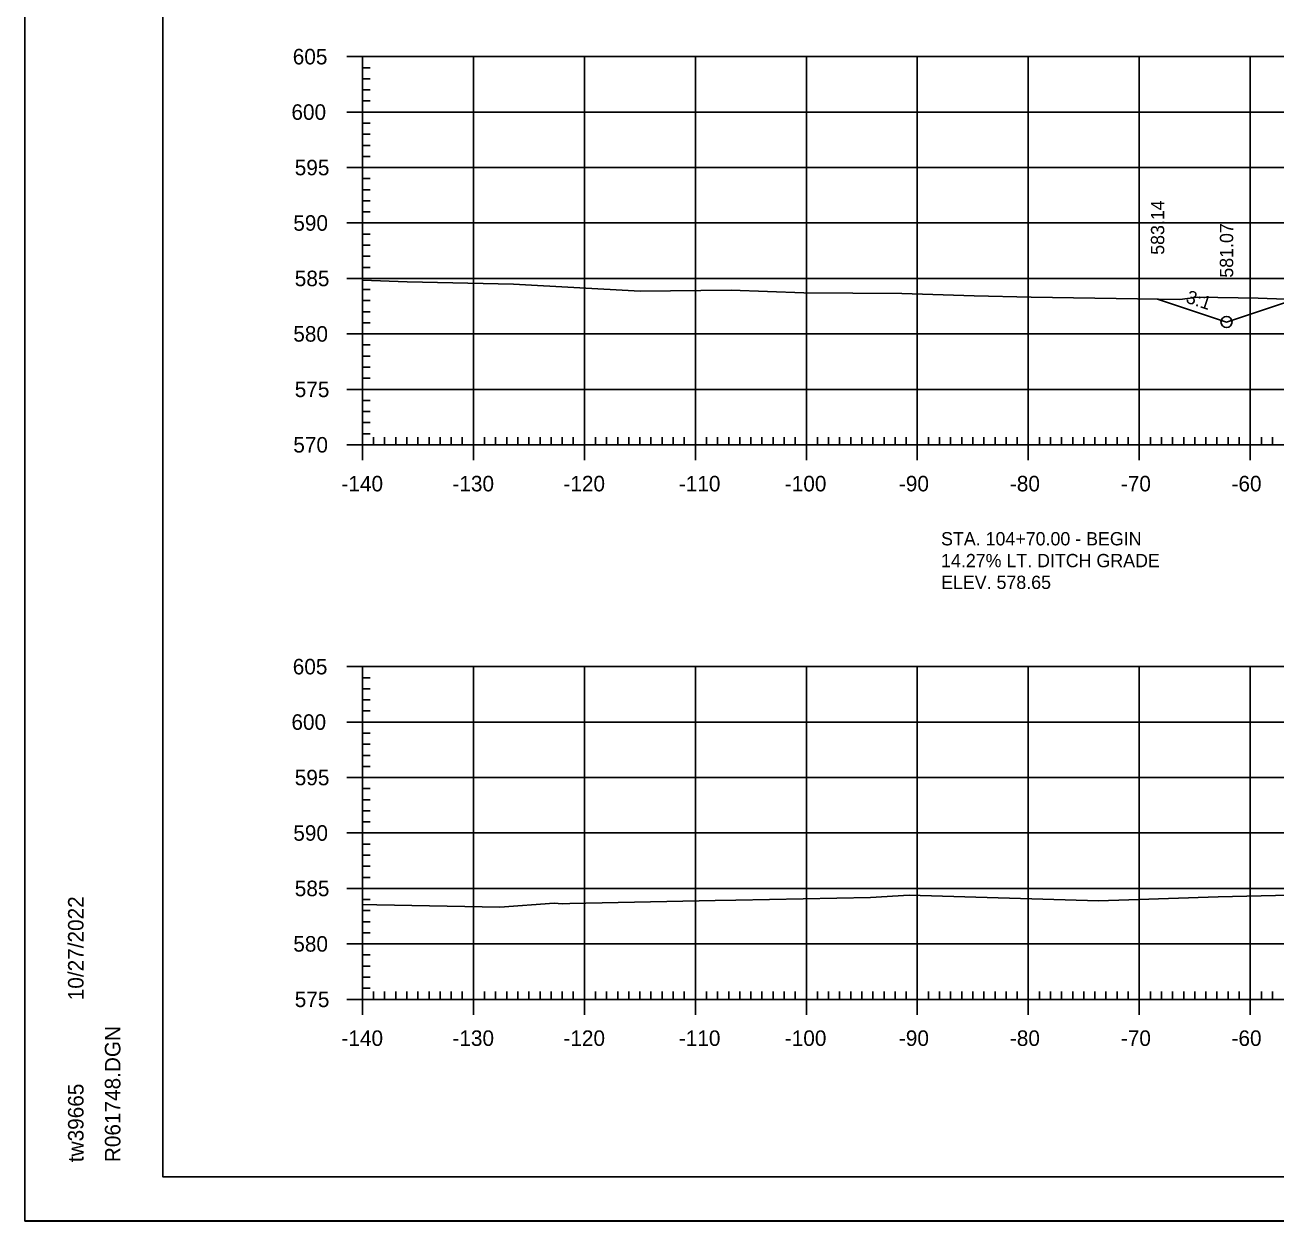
# Model space of a CAD drawing. Extents: x 961436 to 1372525, y 380079 to 2027791.
# Drawn here: x 1370463.4 to 1370576.1, y 380322.4 to 380430.3 of the extents above; entities that cross this region are included whole.
import ezdxf

# ---------------------------------------------------------------- set-up
doc = ezdxf.new("R2010")
doc.units = 0
for name, color, linetype in [('R_Axis', 7, 'Continuous'), ('R_Axis Annot', 7, 'Continuous'), ('R_Exist Surface', 7, 'Continuous'), ('R_Fin Surface', 7, 'Continuous'), ('R_Fin Surface Annot', 7, 'Continuous'), ('R_Grid', 7, 'Continuous'), ('R_No Plot', 7, 'Continuous')]:
    doc.layers.add(name, color=color, linetype=linetype)

msp = doc.modelspace()

# ---------------------------------------------------------------- linework, layer by layer
at = {"layer": 'R_Axis'}
for p, q in [((1370492.41, 380427.4), (1370495.21, 380427.4)), ((1370493.81, 380392.4), (1370493.81, 380427.4)), ((1370493.81, 380426.4), (1370494.51, 380426.4)), ((1370493.81, 380425.4), (1370494.51, 380425.4)), ((1370493.81, 380424.4), (1370494.51, 380424.4)), ((1370493.81, 380423.4), (1370494.51, 380423.4)), ((1370492.41, 380422.4), (1370495.21, 380422.4)), ((1370493.81, 380421.4), (1370494.51, 380421.4)), ((1370493.81, 380420.4), (1370494.51, 380420.4)), ((1370493.81, 380419.4), (1370494.51, 380419.4)), ((1370492.41, 380417.4), (1370495.21, 380417.4)), ((1370493.81, 380418.4), (1370494.51, 380418.4)), ((1370493.81, 380416.4), (1370494.51, 380416.4)), ((1370493.81, 380415.4), (1370494.51, 380415.4)), ((1370493.81, 380414.4), (1370494.51, 380414.4)), ((1370493.81, 380413.4), (1370494.51, 380413.4)), ((1370492.41, 380412.4), (1370495.21, 380412.4)), ((1370493.81, 380411.4), (1370494.51, 380411.4)), ((1370493.81, 380410.4), (1370494.51, 380410.4)), ((1370493.81, 380409.4), (1370494.51, 380409.4)), ((1370493.81, 380408.4), (1370494.51, 380408.4)), ((1370492.41, 380407.4), (1370495.21, 380407.4)), ((1370493.81, 380406.4), (1370494.51, 380406.4)), ((1370493.81, 380405.4), (1370494.51, 380405.4)), ((1370493.81, 380404.4), (1370494.51, 380404.4)), ((1370493.81, 380403.4), (1370494.51, 380403.4)), ((1370492.41, 380402.4), (1370495.21, 380402.4)), ((1370493.81, 380401.4), (1370494.51, 380401.4)), ((1370493.81, 380400.4), (1370494.51, 380400.4)), ((1370493.81, 380399.4), (1370494.51, 380399.4)), ((1370493.81, 380398.4), (1370494.51, 380398.4)), ((1370492.41, 380397.4), (1370495.21, 380397.4)), ((1370493.81, 380396.4), (1370494.51, 380396.4)), ((1370493.81, 380395.4), (1370494.51, 380395.4)), ((1370493.81, 380394.4), (1370494.51, 380394.4)), ((1370493.81, 380391), (1370493.81, 380393.8)), ((1370503.81, 380391), (1370503.81, 380393.8)), ((1370513.81, 380391), (1370513.81, 380393.8)), ((1370523.81, 380391), (1370523.81, 380393.8)), ((1370533.81, 380391), (1370533.81, 380393.8)), ((1370543.81, 380391), (1370543.81, 380393.8)), ((1370553.81, 380391), (1370553.81, 380393.8)), ((1370563.81, 380391), (1370563.81, 380393.8)), ((1370573.81, 380391), (1370573.81, 380393.8)), ((1370493.81, 380393.4), (1370494.51, 380393.4)), ((1370494.81, 380392.4), (1370494.81, 380393.1)), ((1370495.81, 380392.4), (1370495.81, 380393.1)), ((1370496.81, 380392.4), (1370496.81, 380393.1)), ((1370497.81, 380392.4), (1370497.81, 380393.1)), ((1370498.81, 380392.4), (1370498.81, 380393.1)), ((1370499.81, 380392.4), (1370499.81, 380393.1)), ((1370500.81, 380392.4), (1370500.81, 380393.1)), ((1370501.81, 380392.4), (1370501.81, 380393.1)), ((1370502.81, 380392.4), (1370502.81, 380393.1)), ((1370504.81, 380392.4), (1370504.81, 380393.1)), ((1370505.81, 380392.4), (1370505.81, 380393.1)), ((1370506.81, 380392.4), (1370506.81, 380393.1)), ((1370507.81, 380392.4), (1370507.81, 380393.1)), ((1370508.81, 380392.4), (1370508.81, 380393.1)), ((1370509.81, 380392.4), (1370509.81, 380393.1)), ((1370510.81, 380392.4), (1370510.81, 380393.1)), ((1370511.81, 380392.4), (1370511.81, 380393.1)), ((1370512.81, 380392.4), (1370512.81, 380393.1)), ((1370514.81, 380392.4), (1370514.81, 380393.1)), ((1370515.81, 380392.4), (1370515.81, 380393.1)), ((1370516.81, 380392.4), (1370516.81, 380393.1)), ((1370517.81, 380392.4), (1370517.81, 380393.1)), ((1370518.81, 380392.4), (1370518.81, 380393.1)), ((1370519.81, 380392.4), (1370519.81, 380393.1)), ((1370520.81, 380392.4), (1370520.81, 380393.1)), ((1370521.81, 380392.4), (1370521.81, 380393.1)), ((1370522.81, 380392.4), (1370522.81, 380393.1)), ((1370524.81, 380392.4), (1370524.81, 380393.1)), ((1370525.81, 380392.4), (1370525.81, 380393.1)), ((1370526.81, 380392.4), (1370526.81, 380393.1)), ((1370527.81, 380392.4), (1370527.81, 380393.1)), ((1370528.81, 380392.4), (1370528.81, 380393.1)), ((1370529.81, 380392.4), (1370529.81, 380393.1)), ((1370530.81, 380392.4), (1370530.81, 380393.1)), ((1370531.81, 380392.4), (1370531.81, 380393.1)), ((1370532.81, 380392.4), (1370532.81, 380393.1)), ((1370534.81, 380392.4), (1370534.81, 380393.1)), ((1370535.81, 380392.4), (1370535.81, 380393.1)), ((1370536.81, 380392.4), (1370536.81, 380393.1)), ((1370537.81, 380392.4), (1370537.81, 380393.1)), ((1370538.81, 380392.4), (1370538.81, 380393.1)), ((1370539.81, 380392.4), (1370539.81, 380393.1)), ((1370540.81, 380392.4), (1370540.81, 380393.1)), ((1370541.81, 380392.4), (1370541.81, 380393.1)), ((1370542.81, 380392.4), (1370542.81, 380393.1)), ((1370544.81, 380392.4), (1370544.81, 380393.1)), ((1370545.81, 380392.4), (1370545.81, 380393.1)), ((1370546.81, 380392.4), (1370546.81, 380393.1)), ((1370547.81, 380392.4), (1370547.81, 380393.1)), ((1370548.81, 380392.4), (1370548.81, 380393.1)), ((1370549.81, 380392.4), (1370549.81, 380393.1)), ((1370550.81, 380392.4), (1370550.81, 380393.1)), ((1370551.81, 380392.4), (1370551.81, 380393.1)), ((1370552.81, 380392.4), (1370552.81, 380393.1)), ((1370554.81, 380392.4), (1370554.81, 380393.1)), ((1370555.81, 380392.4), (1370555.81, 380393.1)), ((1370556.81, 380392.4), (1370556.81, 380393.1)), ((1370557.81, 380392.4), (1370557.81, 380393.1)), ((1370558.81, 380392.4), (1370558.81, 380393.1)), ((1370559.81, 380392.4), (1370559.81, 380393.1)), ((1370560.81, 380392.4), (1370560.81, 380393.1)), ((1370561.81, 380392.4), (1370561.81, 380393.1)), ((1370562.81, 380392.4), (1370562.81, 380393.1)), ((1370564.81, 380392.4), (1370564.81, 380393.1)), ((1370565.81, 380392.4), (1370565.81, 380393.1)), ((1370566.81, 380392.4), (1370566.81, 380393.1)), ((1370567.81, 380392.4), (1370567.81, 380393.1)), ((1370568.81, 380392.4), (1370568.81, 380393.1)), ((1370569.81, 380392.4), (1370569.81, 380393.1)), ((1370570.81, 380392.4), (1370570.81, 380393.1)), ((1370571.81, 380392.4), (1370571.81, 380393.1)), ((1370572.81, 380392.4), (1370572.81, 380393.1)), ((1370574.81, 380392.4), (1370574.81, 380393.1)), ((1370575.81, 380392.4), (1370575.81, 380393.1)), ((1370492.41, 380392.4), (1370495.21, 380392.4)), ((1370493.81, 380392.4), (1370773.81, 380392.4)), ((1370492.41, 380372.4), (1370495.21, 380372.4)), ((1370493.81, 380342.4), (1370493.81, 380372.4)), ((1370493.81, 380371.4), (1370494.51, 380371.4)), ((1370493.81, 380370.4), (1370494.51, 380370.4)), ((1370493.81, 380369.4), (1370494.51, 380369.4)), ((1370493.81, 380368.4), (1370494.51, 380368.4)), ((1370492.41, 380367.4), (1370495.21, 380367.4)), ((1370493.81, 380366.4), (1370494.51, 380366.4)), ((1370493.81, 380365.4), (1370494.51, 380365.4)), ((1370493.81, 380364.4), (1370494.51, 380364.4)), ((1370493.81, 380363.4), (1370494.51, 380363.4)), ((1370492.41, 380362.4), (1370495.21, 380362.4)), ((1370493.81, 380361.4), (1370494.51, 380361.4)), ((1370493.81, 380360.4), (1370494.51, 380360.4)), ((1370493.81, 380359.4), (1370494.51, 380359.4)), ((1370493.81, 380358.4), (1370494.51, 380358.4)), ((1370492.41, 380357.4), (1370495.21, 380357.4)), ((1370493.81, 380356.4), (1370494.51, 380356.4)), ((1370493.81, 380355.4), (1370494.51, 380355.4)), ((1370493.81, 380354.4), (1370494.51, 380354.4)), ((1370493.81, 380353.4), (1370494.51, 380353.4)), ((1370492.41, 380352.4), (1370495.21, 380352.4)), ((1370493.81, 380351.4), (1370494.51, 380351.4)), ((1370493.81, 380350.4), (1370494.51, 380350.4)), ((1370493.81, 380349.4), (1370494.51, 380349.4)), ((1370493.81, 380348.4), (1370494.51, 380348.4)), ((1370492.41, 380347.4), (1370495.21, 380347.4)), ((1370493.81, 380346.4), (1370494.51, 380346.4)), ((1370493.81, 380345.4), (1370494.51, 380345.4)), ((1370493.81, 380344.4), (1370494.51, 380344.4)), ((1370493.81, 380341), (1370493.81, 380343.8)), ((1370493.81, 380343.4), (1370494.51, 380343.4)), ((1370494.81, 380342.4), (1370494.81, 380343.1)), ((1370495.81, 380342.4), (1370495.81, 380343.1)), ((1370496.81, 380342.4), (1370496.81, 380343.1)), ((1370497.81, 380342.4), (1370497.81, 380343.1)), ((1370498.81, 380342.4), (1370498.81, 380343.1)), ((1370499.81, 380342.4), (1370499.81, 380343.1)), ((1370500.81, 380342.4), (1370500.81, 380343.1)), ((1370501.81, 380342.4), (1370501.81, 380343.1)), ((1370502.81, 380342.4), (1370502.81, 380343.1)), ((1370503.81, 380341), (1370503.81, 380343.8)), ((1370504.81, 380342.4), (1370504.81, 380343.1)), ((1370505.81, 380342.4), (1370505.81, 380343.1)), ((1370506.81, 380342.4), (1370506.81, 380343.1)), ((1370507.81, 380342.4), (1370507.81, 380343.1)), ((1370508.81, 380342.4), (1370508.81, 380343.1)), ((1370509.81, 380342.4), (1370509.81, 380343.1)), ((1370510.81, 380342.4), (1370510.81, 380343.1)), ((1370511.81, 380342.4), (1370511.81, 380343.1)), ((1370512.81, 380342.4), (1370512.81, 380343.1)), ((1370513.81, 380341), (1370513.81, 380343.8)), ((1370514.81, 380342.4), (1370514.81, 380343.1)), ((1370515.81, 380342.4), (1370515.81, 380343.1)), ((1370516.81, 380342.4), (1370516.81, 380343.1)), ((1370517.81, 380342.4), (1370517.81, 380343.1)), ((1370518.81, 380342.4), (1370518.81, 380343.1)), ((1370519.81, 380342.4), (1370519.81, 380343.1)), ((1370520.81, 380342.4), (1370520.81, 380343.1)), ((1370521.81, 380342.4), (1370521.81, 380343.1)), ((1370522.81, 380342.4), (1370522.81, 380343.1)), ((1370523.81, 380341), (1370523.81, 380343.8)), ((1370524.81, 380342.4), (1370524.81, 380343.1)), ((1370525.81, 380342.4), (1370525.81, 380343.1)), ((1370526.81, 380342.4), (1370526.81, 380343.1)), ((1370527.81, 380342.4), (1370527.81, 380343.1)), ((1370528.81, 380342.4), (1370528.81, 380343.1)), ((1370529.81, 380342.4), (1370529.81, 380343.1)), ((1370530.81, 380342.4), (1370530.81, 380343.1)), ((1370531.81, 380342.4), (1370531.81, 380343.1)), ((1370532.81, 380342.4), (1370532.81, 380343.1)), ((1370533.81, 380341), (1370533.81, 380343.8)), ((1370534.81, 380342.4), (1370534.81, 380343.1)), ((1370535.81, 380342.4), (1370535.81, 380343.1)), ((1370536.81, 380342.4), (1370536.81, 380343.1)), ((1370537.81, 380342.4), (1370537.81, 380343.1)), ((1370538.81, 380342.4), (1370538.81, 380343.1)), ((1370539.81, 380342.4), (1370539.81, 380343.1)), ((1370540.81, 380342.4), (1370540.81, 380343.1)), ((1370541.81, 380342.4), (1370541.81, 380343.1)), ((1370542.81, 380342.4), (1370542.81, 380343.1)), ((1370543.81, 380341), (1370543.81, 380343.8)), ((1370544.81, 380342.4), (1370544.81, 380343.1)), ((1370545.81, 380342.4), (1370545.81, 380343.1)), ((1370546.81, 380342.4), (1370546.81, 380343.1)), ((1370547.81, 380342.4), (1370547.81, 380343.1)), ((1370548.81, 380342.4), (1370548.81, 380343.1)), ((1370549.81, 380342.4), (1370549.81, 380343.1)), ((1370550.81, 380342.4), (1370550.81, 380343.1)), ((1370551.81, 380342.4), (1370551.81, 380343.1)), ((1370552.81, 380342.4), (1370552.81, 380343.1)), ((1370553.81, 380341), (1370553.81, 380343.8)), ((1370554.81, 380342.4), (1370554.81, 380343.1)), ((1370555.81, 380342.4), (1370555.81, 380343.1)), ((1370556.81, 380342.4), (1370556.81, 380343.1)), ((1370557.81, 380342.4), (1370557.81, 380343.1)), ((1370558.81, 380342.4), (1370558.81, 380343.1)), ((1370559.81, 380342.4), (1370559.81, 380343.1)), ((1370560.81, 380342.4), (1370560.81, 380343.1)), ((1370561.81, 380342.4), (1370561.81, 380343.1)), ((1370562.81, 380342.4), (1370562.81, 380343.1)), ((1370563.81, 380341), (1370563.81, 380343.8)), ((1370564.81, 380342.4), (1370564.81, 380343.1)), ((1370565.81, 380342.4), (1370565.81, 380343.1)), ((1370566.81, 380342.4), (1370566.81, 380343.1)), ((1370567.81, 380342.4), (1370567.81, 380343.1)), ((1370568.81, 380342.4), (1370568.81, 380343.1)), ((1370569.81, 380342.4), (1370569.81, 380343.1)), ((1370570.81, 380342.4), (1370570.81, 380343.1)), ((1370571.81, 380342.4), (1370571.81, 380343.1)), ((1370572.81, 380342.4), (1370572.81, 380343.1)), ((1370573.81, 380341), (1370573.81, 380343.8)), ((1370574.81, 380342.4), (1370574.81, 380343.1)), ((1370575.81, 380342.4), (1370575.81, 380343.1)), ((1370492.41, 380342.4), (1370495.21, 380342.4)), ((1370493.81, 380342.4), (1370773.81, 380342.4))]:
    msp.add_line(p, q, dxfattribs=at)
at = {"layer": 'R_Exist Surface'}
for points in [[(1370493.81, 380407.24), (1370497.83, 380407.1), (1370507.43, 380406.87), (1370518.84, 380406.24), (1370527.04, 380406.35), (1370533.59, 380406.11), (1370542.42, 380406.05), (1370548.92, 380405.82), (1370554.07, 380405.71), (1370567.47, 380405.5), (1370569.09, 380405.71), (1370574.52, 380405.61), (1370588.55, 380405.1)], [(1370493.81, 380350.96), (1370495.11, 380350.93), (1370506.18, 380350.72), (1370511.08, 380351.06), (1370511.81, 380351.02), (1370512.5, 380351.03), (1370525.59, 380351.3), (1370527.45, 380351.34), (1370539.6, 380351.58), (1370543.08, 380351.79), (1370560.13, 380351.29), (1370562.86, 380351.36), (1370570.92, 380351.63), (1370576.07, 380351.75), (1370584.56, 380351.96)]]:
    msp.add_lwpolyline(points, dxfattribs=at)
at = {"layer": 'R_Fin Surface'}
msp.add_lwpolyline([(1370565.46, 380405.53), (1370569.6, 380404.16), (1370571.67, 380403.47), (1370585.42, 380408.05), (1370597.81, 380412.18), (1370606.53, 380415.09), (1370614.33, 380417.69), (1370617.31, 380418.68), (1370624.81, 380418.98), (1370633.81, 380419.16), (1370642.81, 380418.98), (1370650.31, 380418.68), (1370653.07, 380417.76), (1370661.12, 380415.08), (1370671.96, 380411.46), (1370694.35, 380404), (1370695.57, 380403.59), (1370697.15, 380403.07), (1370698.39, 380402.65), (1370699.12, 380402.41)], dxfattribs=at)
at = {"layer": 'R_Grid'}
for p, q in [((1370493.81, 380427.4), (1370773.81, 380427.4)), ((1370493.81, 380392.4), (1370493.81, 380427.4)), ((1370503.81, 380392.4), (1370503.81, 380427.4)), ((1370513.81, 380392.4), (1370513.81, 380427.4)), ((1370523.81, 380392.4), (1370523.81, 380427.4)), ((1370533.81, 380392.4), (1370533.81, 380427.4)), ((1370543.81, 380392.4), (1370543.81, 380427.4)), ((1370553.81, 380392.4), (1370553.81, 380427.4)), ((1370563.81, 380392.4), (1370563.81, 380427.4)), ((1370573.81, 380392.4), (1370573.81, 380427.4)), ((1370493.81, 380422.4), (1370773.81, 380422.4)), ((1370493.81, 380417.4), (1370773.81, 380417.4)), ((1370493.81, 380412.4), (1370773.81, 380412.4)), ((1370493.81, 380407.4), (1370773.81, 380407.4)), ((1370493.81, 380402.4), (1370773.81, 380402.4)), ((1370493.81, 380397.4), (1370773.81, 380397.4)), ((1370493.81, 380392.4), (1370773.81, 380392.4)), ((1370493.81, 380372.4), (1370773.81, 380372.4)), ((1370493.81, 380342.4), (1370493.81, 380372.4)), ((1370503.81, 380342.4), (1370503.81, 380372.4)), ((1370513.81, 380342.4), (1370513.81, 380372.4)), ((1370523.81, 380342.4), (1370523.81, 380372.4)), ((1370533.81, 380342.4), (1370533.81, 380372.4)), ((1370543.81, 380342.4), (1370543.81, 380372.4)), ((1370553.81, 380342.4), (1370553.81, 380372.4)), ((1370563.81, 380342.4), (1370563.81, 380372.4)), ((1370573.81, 380342.4), (1370573.81, 380372.4)), ((1370493.81, 380367.4), (1370773.81, 380367.4)), ((1370493.81, 380362.4), (1370773.81, 380362.4)), ((1370493.81, 380357.4), (1370773.81, 380357.4)), ((1370493.81, 380352.4), (1370773.81, 380352.4)), ((1370493.81, 380347.4), (1370773.81, 380347.4)), ((1370493.81, 380342.4), (1370773.81, 380342.4))]:
    msp.add_line(p, q, dxfattribs=at)
at = {"layer": 'R_No Plot'}
for p, q in [((1370475.81, 380326.4), (1370475.81, 380531.86)), ((1370475.81, 380326.4), (1370475.81, 380326.4)), ((1370791.99, 380326.4), (1370475.81, 380326.4)), ((1370463.41, 380322.42), (1370796.74, 380322.42))]:
    msp.add_line(p, q, dxfattribs=at)
for points in [[(1370463.4, 380535.75), (1370796.74, 380535.75), (1370796.74, 380322.41), (1370463.4, 380322.41)], [(1370709.73, 380531.86), (1370729.35, 380531.86), (1370729.35, 380521.98), (1370745.46, 380521.98), (1370768.66, 380521.98), (1370768.78, 380493.82), (1370791.99, 380493.82), (1370791.99, 380326.4), (1370475.81, 380326.4), (1370475.81, 380531.86)]]:
    msp.add_lwpolyline(points, close=True, dxfattribs=at)
msp.add_circle((1370571.67, 380403.47), 0.5, dxfattribs=at)

# ---------------------------------------------------------------- texts
at = {"layer": 'R_Axis Annot'}
for s, p in [('605', (1370487.53, 380426.7)), ('600', (1370487.41, 380421.7)), ('595', (1370487.71, 380416.7)), ('590', (1370487.58, 380411.7)), ('585', (1370487.71, 380406.7)), ('580', (1370487.58, 380401.7)), ('575', (1370487.71, 380396.7)), ('570', (1370487.58, 380391.7)), ('-140', (1370491.92, 380388.2)), ('-130', (1370501.92, 380388.2)), ('-120', (1370511.92, 380388.2)), ('-110', (1370522.32, 380388.2)), ('-100', (1370531.87, 380388.2)), ('-90', (1370542.15, 380388.2)), ('-80', (1370552.15, 380388.2)), ('-70', (1370562.15, 380388.2)), ('-60', (1370572.12, 380388.2)), ('605', (1370487.53, 380371.7)), ('600', (1370487.41, 380366.7)), ('595', (1370487.71, 380361.7)), ('590', (1370487.58, 380356.7)), ('585', (1370487.71, 380351.7)), ('580', (1370487.58, 380346.7)), ('575', (1370487.71, 380341.7)), ('-140', (1370491.92, 380338.2)), ('-130', (1370501.92, 380338.2)), ('-120', (1370511.92, 380338.2)), ('-110', (1370522.32, 380338.2)), ('-100', (1370531.87, 380338.2)), ('-90', (1370542.15, 380338.2)), ('-80', (1370552.15, 380338.2)), ('-70', (1370562.15, 380338.2)), ('-60', (1370572.12, 380338.2))]:
    msp.add_text(s, height=1.4, dxfattribs=at).set_placement(p)
at = {"layer": 'R_Fin Surface Annot'}
for s, rotation, p in [('583.14', 90, (1370566.06, 380409.53)), ('581.07', 90, (1370572.27, 380407.47)), ('3:1', 341.5651, (1370567.93, 380405.24))]:
    msp.add_text(s, height=1.2, rotation=rotation, dxfattribs=at).set_placement(p)
for s, p in [('STA. 104+70.00 - BEGIN', (1370545.95, 380383.33)), ('14.27% LT. DITCH GRADE', (1370545.95, 380381.36)), ('ELEV. 578.65', (1370545.95, 380379.4))]:
    msp.add_text(s, height=1.2, dxfattribs=at).set_placement(p)
at = {"layer": 'R_No Plot'}
for s, p in [('10/27/2022', (1370468.68, 380342.32)), ('R061748.DGN', (1370472, 380327.72)), ('tw39665', (1370468.68, 380327.72))]:
    msp.add_text(s, height=1.4, rotation=90, dxfattribs=at).set_placement(p)

doc.saveas('drawing.dxf')
